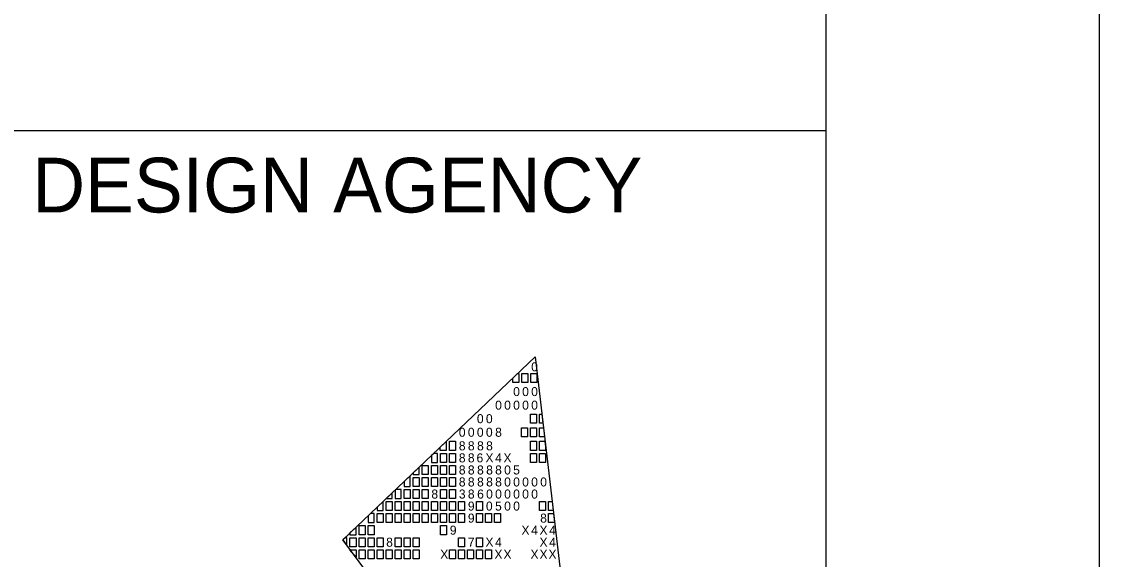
# Model space of a CAD drawing. Extents: x -18.6 to 78.7, y 0 to 36.9.
# Drawn here: x 32.03 to 34, y 3.716 to 4.699 of the extents above; entities that cross this region are included whole.
import ezdxf

# ---------------------------------------------------------------- set-up
doc = ezdxf.new("R2010")
doc.units = 0
for name, color, linetype in [('SH_Border', 7, 'Continuous'), ('SH_Cut_Line', 7, 'Continuous'), ('SH_Data', 7, 'Continuous')]:
    doc.layers.add(name, color=color, linetype=linetype)

msp = doc.modelspace()

# ---------------------------------------------------------------- linework, layer by layer
at = {"layer": 'SH_Border'}
for p, q in [((32, 4.5), (33.5, 4.5)), ((32.6175, 3.7519), (32.9688, 4.0861)), ((32.9688, 4.0861), (32.9688, 4.0861)), ((32.9688, 4.0861), (33.0253, 3.6052)), ((32.773, 3.543), (32.6175, 3.7519))]:
    msp.add_line(p, q, dxfattribs=at)
for points in [[(1.5, 21.5), (33.5, 21.5), (33.5, 0.5), (1.5, 0.5)], [(32.9279, 4.0472), (32.9369, 4.0558), (32.9389, 4.0558), (32.9389, 4.0393), (32.9279, 4.0393)], [(32.9444, 4.0558), (32.9554, 4.0558), (32.9554, 4.0393), (32.9444, 4.0393)], [(32.9609, 4.0558), (32.9719, 4.0558), (32.9719, 4.0393), (32.9609, 4.0393)], [(32.9606, 3.9815), (32.9716, 3.9815), (32.9716, 3.965), (32.9606, 3.965)], [(32.9771, 3.9815), (32.9811, 3.9815), (32.983, 3.965), (32.9771, 3.965)], [(32.9441, 3.9567), (32.9551, 3.9567), (32.9551, 3.9402), (32.9441, 3.9402)], [(32.9606, 3.9567), (32.9716, 3.9567), (32.9716, 3.9402), (32.9606, 3.9402)], [(32.9771, 3.9567), (32.984, 3.9567), (32.9859, 3.9402), (32.9771, 3.9402)], [(32.7953, 3.9211), (32.8064, 3.9316), (32.8064, 3.9154), (32.7953, 3.9154)], [(32.8123, 3.9319), (32.8233, 3.9319), (32.8233, 3.9154), (32.8123, 3.9154)], [(32.9606, 3.9319), (32.9716, 3.9319), (32.9716, 3.9154), (32.9606, 3.9154)], [(32.9771, 3.9319), (32.9869, 3.9319), (32.9881, 3.9218), (32.9881, 3.9154), (32.9771, 3.9154)], [(32.7958, 3.9099), (32.8068, 3.9099), (32.8068, 3.8934), (32.7958, 3.8934)], [(32.8123, 3.9099), (32.8233, 3.9099), (32.8233, 3.8934), (32.8123, 3.8934)], [(32.9606, 3.9099), (32.9716, 3.9099), (32.9716, 3.8934), (32.9606, 3.8934)], [(32.9771, 3.9099), (32.9881, 3.9099), (32.9881, 3.8934), (32.9771, 3.8934)], [(32.7627, 3.8879), (32.7737, 3.8879), (32.7737, 3.8714), (32.7627, 3.8714)], [(32.7793, 3.8879), (32.7903, 3.8879), (32.7903, 3.8714), (32.7793, 3.8714)], [(32.7958, 3.8879), (32.8068, 3.8879), (32.8068, 3.8714), (32.7958, 3.8714)], [(32.8123, 3.8879), (32.8233, 3.8879), (32.8233, 3.8714), (32.8123, 3.8714)], [(32.7462, 3.8659), (32.7572, 3.8659), (32.7572, 3.8494), (32.7462, 3.8494)], [(32.7627, 3.8659), (32.7737, 3.8659), (32.7737, 3.8494), (32.7627, 3.8494)], [(32.7793, 3.8659), (32.7903, 3.8659), (32.7903, 3.8494), (32.7793, 3.8494)], [(32.7958, 3.8659), (32.8068, 3.8659), (32.8068, 3.8494), (32.7958, 3.8494)], [(32.8123, 3.8659), (32.8233, 3.8659), (32.8233, 3.8494), (32.8123, 3.8494)], [(32.7297, 3.8439), (32.7407, 3.8439), (32.7407, 3.8273), (32.7297, 3.8273)], [(32.7462, 3.8439), (32.7572, 3.8439), (32.7572, 3.8273), (32.7462, 3.8273)], [(32.7627, 3.8439), (32.7737, 3.8439), (32.7737, 3.8273), (32.7627, 3.8273)], [(32.7958, 3.8439), (32.8068, 3.8439), (32.8068, 3.8273), (32.7958, 3.8273)], [(32.8123, 3.8439), (32.8233, 3.8439), (32.8233, 3.8273), (32.8123, 3.8273)], [(32.6967, 3.8218), (32.7077, 3.8218), (32.7077, 3.8053), (32.6967, 3.8053)], [(32.7132, 3.8218), (32.7242, 3.8218), (32.7242, 3.8053), (32.7132, 3.8053)], [(32.7297, 3.8218), (32.7407, 3.8218), (32.7407, 3.8053), (32.7297, 3.8053)], [(32.7462, 3.8218), (32.7572, 3.8218), (32.7572, 3.8053), (32.7462, 3.8053)], [(32.7627, 3.8218), (32.7737, 3.8218), (32.7737, 3.8053), (32.7627, 3.8053)], [(32.7793, 3.8218), (32.7903, 3.8218), (32.7903, 3.8053), (32.7793, 3.8053)], [(32.7958, 3.8218), (32.8068, 3.8218), (32.8068, 3.8053), (32.7958, 3.8053)], [(32.8123, 3.8218), (32.8233, 3.8218), (32.8233, 3.8053), (32.8123, 3.8053)], [(32.8288, 3.8218), (32.8398, 3.8218), (32.8398, 3.8053), (32.8288, 3.8053)], [(32.8618, 3.8218), (32.8728, 3.8218), (32.8728, 3.8053), (32.8618, 3.8053)], [(32.9771, 3.8218), (32.9881, 3.8218), (32.9881, 3.8053), (32.9771, 3.8053)], [(32.9935, 3.8218), (32.9998, 3.8218), (33.0018, 3.8053), (32.9935, 3.8053)], [(32.6802, 3.7998), (32.6912, 3.7998), (32.6912, 3.7833), (32.6802, 3.7833)], [(32.6967, 3.7998), (32.7077, 3.7998), (32.7077, 3.7833), (32.6967, 3.7833)], [(32.7132, 3.7998), (32.7242, 3.7998), (32.7242, 3.7833), (32.7132, 3.7833)], [(32.7297, 3.7998), (32.7407, 3.7998), (32.7407, 3.7833), (32.7297, 3.7833)], [(32.7462, 3.7998), (32.7572, 3.7998), (32.7572, 3.7833), (32.7462, 3.7833)], [(32.7627, 3.7998), (32.7737, 3.7998), (32.7737, 3.7833), (32.7627, 3.7833)], [(32.7793, 3.7998), (32.7903, 3.7998), (32.7903, 3.7833), (32.7793, 3.7833)], [(32.7958, 3.7998), (32.8068, 3.7998), (32.8068, 3.7833), (32.7958, 3.7833)], [(32.8123, 3.7998), (32.8233, 3.7998), (32.8233, 3.7833), (32.8123, 3.7833)], [(32.8288, 3.7998), (32.8398, 3.7998), (32.8398, 3.7833), (32.8288, 3.7833)], [(32.8618, 3.7998), (32.8728, 3.7998), (32.8728, 3.7833), (32.8618, 3.7833)], [(32.8783, 3.7998), (32.8893, 3.7998), (32.8893, 3.7833), (32.8783, 3.7833)], [(32.8947, 3.7998), (32.9057, 3.7998), (32.9057, 3.7833), (32.8947, 3.7833)], [(32.9935, 3.7998), (33.0024, 3.7998), (33.0044, 3.7833), (32.9935, 3.7833)], [(32.6471, 3.7778), (32.6581, 3.7778), (32.6581, 3.7613), (32.6471, 3.7613)], [(32.6637, 3.7778), (32.6747, 3.7778), (32.6747, 3.7613), (32.6637, 3.7613)], [(32.7958, 3.7778), (32.8068, 3.7778), (32.8068, 3.7613), (32.7958, 3.7613)], [(32.6306, 3.7558), (32.6416, 3.7558), (32.6416, 3.7393), (32.6306, 3.7393)], [(32.6471, 3.7558), (32.6581, 3.7558), (32.6581, 3.7393), (32.6471, 3.7393)], [(32.6637, 3.7558), (32.6747, 3.7558), (32.6747, 3.7393), (32.6637, 3.7393)], [(32.6802, 3.7558), (32.6912, 3.7558), (32.6912, 3.7393), (32.6802, 3.7393)], [(32.7132, 3.7558), (32.7242, 3.7558), (32.7242, 3.7393), (32.7132, 3.7393)], [(32.7297, 3.7558), (32.7407, 3.7558), (32.7407, 3.7393), (32.7297, 3.7393)], [(32.7462, 3.7558), (32.7572, 3.7558), (32.7572, 3.7393), (32.7462, 3.7393)], [(32.8288, 3.7558), (32.8398, 3.7558), (32.8398, 3.7393), (32.8288, 3.7393)], [(32.8618, 3.7558), (32.8728, 3.7558), (32.8728, 3.7393), (32.8618, 3.7393)], [(32.6306, 3.7338), (32.6416, 3.7338), (32.6416, 3.72)], [(32.6471, 3.7338), (32.6581, 3.7338), (32.6581, 3.7173), (32.6471, 3.7173)], [(32.6637, 3.7338), (32.6747, 3.7338), (32.6747, 3.7173), (32.6637, 3.7173)], [(32.6802, 3.7338), (32.6912, 3.7338), (32.6912, 3.7173), (32.6802, 3.7173)], [(32.6967, 3.7338), (32.7077, 3.7338), (32.7077, 3.7173), (32.6967, 3.7173)], [(32.7132, 3.7338), (32.7242, 3.7338), (32.7242, 3.7173), (32.7132, 3.7173)], [(32.7297, 3.7338), (32.7407, 3.7338), (32.7407, 3.7173), (32.7297, 3.7173)], [(32.7462, 3.7338), (32.7572, 3.7338), (32.7572, 3.7173), (32.7462, 3.7173)], [(32.8123, 3.7338), (32.8233, 3.7338), (32.8233, 3.7173), (32.8123, 3.7173)], [(32.8288, 3.7338), (32.8398, 3.7338), (32.8398, 3.7173), (32.8288, 3.7173)], [(32.8453, 3.7338), (32.8563, 3.7338), (32.8563, 3.7173), (32.8453, 3.7173)], [(32.8618, 3.7338), (32.8728, 3.7338), (32.8728, 3.7173), (32.8618, 3.7173)], [(32.8783, 3.7338), (32.8893, 3.7338), (32.8893, 3.7173), (32.8783, 3.7173)]]:
    msp.add_lwpolyline(points, close=True, dxfattribs=at)
for points in [[(32.7903, 3.9099), (32.7836, 3.9099), (32.7793, 3.9058), (32.7793, 3.8934), (32.7903, 3.8934), (32.7903, 3.9099)], [(32.7572, 3.8849), (32.7462, 3.8744), (32.7462, 3.8714), (32.7572, 3.8714), (32.7572, 3.8849)], [(32.7407, 3.8691), (32.7297, 3.8587), (32.7297, 3.8494), (32.7407, 3.8494), (32.7407, 3.8691)], [(32.7242, 3.8439), (32.7141, 3.8439), (32.7132, 3.843), (32.7132, 3.8273), (32.7242, 3.8273), (32.7242, 3.8439)], [(32.6912, 3.822), (32.6802, 3.8115), (32.6802, 3.8053), (32.6912, 3.8053), (32.6912, 3.822)], [(32.7077, 3.8377), (32.6968, 3.8273), (32.7077, 3.8273), (32.7077, 3.8377)], [(32.6747, 3.7998), (32.6679, 3.7998), (32.6637, 3.7958), (32.6637, 3.7833), (32.6747, 3.7833), (32.6747, 3.7998)], [(32.6416, 3.7749), (32.6306, 3.7644), (32.6306, 3.7613), (32.6416, 3.7613), (32.6416, 3.7749)], [(32.6251, 3.7558), (32.6216, 3.7558), (32.6175, 3.7519), (32.6251, 3.7417), (32.6251, 3.7558)]]:
    msp.add_lwpolyline(points, dxfattribs=at)
at = {"layer": 'SH_Cut_Line'}
msp.add_lwpolyline([(0, 0), (34, 0), (34, 22), (0, 22)], close=True, dxfattribs=at)

# ---------------------------------------------------------------- texts
at = {"layer": 'SH_Border'}
for s, p in [('0', (32.9617, 4.0597)), ('0', (32.9288, 4.0145)), ('0', (32.9452, 4.0145)), ('0', (32.9617, 4.0145)), ('0', (32.8958, 3.9897)), ('0', (32.9123, 3.9897)), ('0', (32.9288, 3.9897)), ('0', (32.9452, 3.9897)), ('0', (32.9617, 3.9897)), ('0', (32.8625, 3.965)), ('0', (32.879, 3.965)), ('0', (32.8295, 3.9402)), ('0', (32.846, 3.9402)), ('0', (32.8625, 3.9402)), ('0', (32.879, 3.9402)), ('8', (32.8958, 3.9402)), ('8', (32.8295, 3.9154)), ('8', (32.846, 3.9154)), ('8', (32.8628, 3.9154)), ('8', (32.8793, 3.9154)), ('8', (32.8295, 3.8934)), ('8', (32.846, 3.8934)), ('6', (32.8618, 3.8934)), ('X', (32.8781, 3.8934)), ('4', (32.8958, 3.8934)), ('X', (32.911, 3.8934)), ('8', (32.8295, 3.8713)), ('8', (32.846, 3.8713)), ('8', (32.8628, 3.8713)), ('8', (32.8794, 3.8713)), ('8', (32.8958, 3.8713)), ('0', (32.9123, 3.8713)), ('5', (32.9287, 3.8713)), ('8', (32.8295, 3.8494)), ('8', (32.846, 3.8494)), ('8', (32.8628, 3.8494)), ('8', (32.8794, 3.8494)), ('8', (32.8958, 3.8494)), ('0', (32.9123, 3.8494)), ('0', (32.9288, 3.8494)), ('0', (32.9452, 3.8494)), ('0', (32.9617, 3.8494)), ('0', (32.9782, 3.8494)), ('8', (32.7793, 3.8273)), ('3', (32.8295, 3.8273)), ('8', (32.846, 3.8273)), ('6', (32.8629, 3.8273)), ('0', (32.8793, 3.8273)), ('0', (32.8958, 3.8273)), ('0', (32.9123, 3.8273)), ('0', (32.9288, 3.8273)), ('0', (32.9452, 3.8273)), ('0', (32.9617, 3.8273)), ('9', (32.846, 3.8053)), ('0', (32.879, 3.8053)), ('5', (32.8957, 3.8053)), ('0', (32.9123, 3.8053)), ('0', (32.9288, 3.8053)), ('9', (32.846, 3.7833)), ('8', (32.9781, 3.7833)), ('9', (32.813, 3.7613)), ('X', (32.9439, 3.7613)), ('4', (32.9617, 3.7613)), ('X', (32.9769, 3.7613)), ('4', (32.9946, 3.7613)), ('8', (32.6967, 3.7393)), ('7', (32.846, 3.7393)), ('X', (32.8781, 3.7393)), ('4', (32.8958, 3.7393)), ('X', (32.9769, 3.7393)), ('4', (32.9946, 3.7393)), ('X', (32.7955, 3.7173)), ('X', (32.8945, 3.7173)), ('X', (32.911, 3.7173)), ('X', (32.9604, 3.7173)), ('X', (32.9769, 3.7173)), ('X', (32.9933, 3.7173))]:
    msp.add_text(s, height=0.0165, rotation=360, dxfattribs=at).set_placement(p)
at = {"layer": 'SH_Data'}
msp.add_text('DESIGN AGENCY', height=0.1, dxfattribs=at).set_placement((32.05, 4.35))

doc.saveas('drawing.dxf')
